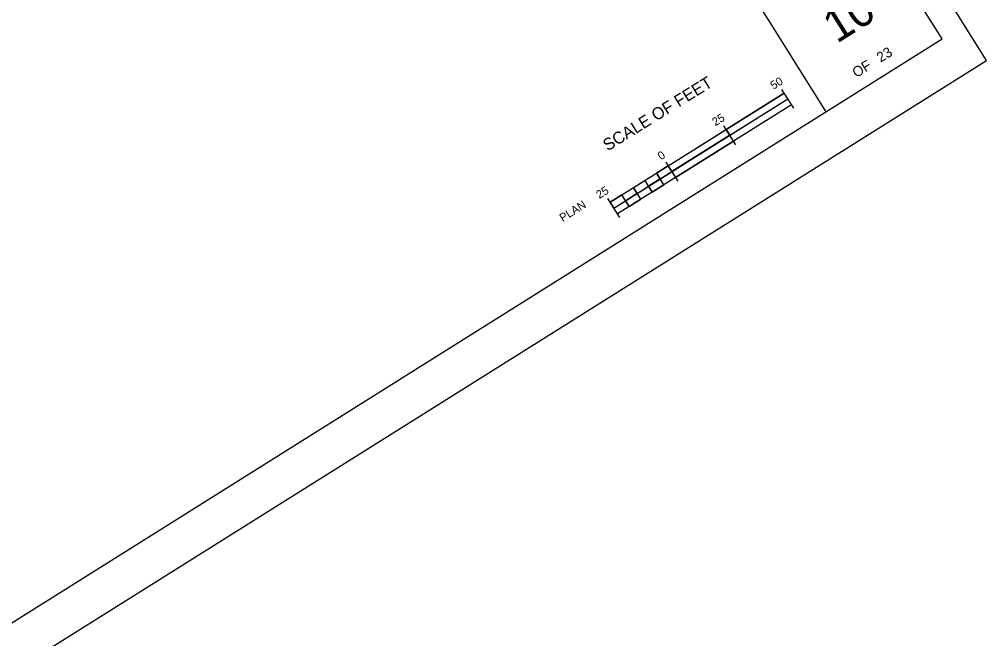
# Model space of a CAD drawing. Extents: x 1667656 to 1668829, y 338796 to 339856.
# Drawn here: x 1668476 to 1668829.2, y 339178.8 to 339404.8 of the extents above; entities that cross this region are included whole.
import ezdxf

# ---------------------------------------------------------------- set-up
doc = ezdxf.new("R2010")
doc.units = 0
for name, color, linetype in [('Asbuilts', 7, 'Continuous'), ('BORDER', 7, 'Continuous'), ('H_V CONTROLS', 7, 'Continuous'), ('PLOT BOUNDARY', 7, 'Continuous')]:
    doc.layers.add(name, color=color, linetype=linetype)

msp = doc.modelspace()

# ---------------------------------------------------------------- linework, layer by layer
at = {"layer": 'Asbuilts'}
msp.add_line((1668755.32, 339377.93), (1668722.75, 339357.5), dxfattribs=at)
at = {"layer": 'BORDER'}
for p, q in [((1668813.03, 339397.69), (1668534.13, 339842.48)), ((1668770.67, 339371.11), (1668491.76, 339815.92)), ((1668135.26, 338972.68), (1668813.03, 339397.67))]:
    msp.add_line(p, q, dxfattribs=at)
at = {"layer": 'H_V CONTROLS'}
for p, q in [((1668758.8, 339372.37), (1668754.49, 339379.25)), ((1668691.78, 339338.08), (1668755.32, 339377.93)), ((1668693.1, 339335.96), (1668756.64, 339375.81)), ((1668757.97, 339373.69), (1668694.43, 339333.85)), ((1668737.62, 339359.08), (1668733.31, 339365.97)), ((1668712.13, 339352.69), (1668716.44, 339345.8)), ((1668711.38, 339344.47), (1668708.72, 339348.71)), ((1668707.14, 339341.81), (1668704.48, 339346.05)), ((1668698.67, 339336.5), (1668696.01, 339340.74)), ((1668702.9, 339339.16), (1668700.25, 339343.39)), ((1668695.26, 339332.52), (1668690.95, 339339.41))]:
    msp.add_line(p, q, dxfattribs=at)
for points in [[(1668735.46, 339362.53), (1668756.64, 339375.81), (1668755.32, 339377.93), (1668734.14, 339364.64), (1668735.46, 339362.53)], [(1668735.46, 339362.53), (1668714.28, 339349.25), (1668715.61, 339347.13), (1668736.79, 339360.41), (1668735.46, 339362.53)], [(1668710.05, 339346.59), (1668714.28, 339349.25), (1668712.96, 339351.36), (1668708.72, 339348.71), (1668710.05, 339346.59)], [(1668705.81, 339343.93), (1668704.48, 339346.05), (1668700.25, 339343.39), (1668701.58, 339341.28), (1668705.81, 339343.93)], [(1668705.81, 339343.93), (1668707.14, 339341.81), (1668711.38, 339344.47), (1668710.05, 339346.59), (1668705.81, 339343.93)], [(1668697.34, 339338.62), (1668696.01, 339340.74), (1668691.78, 339338.08), (1668693.1, 339335.96), (1668697.34, 339338.62)], [(1668697.34, 339338.62), (1668698.67, 339336.5), (1668702.9, 339339.16), (1668701.58, 339341.28), (1668697.34, 339338.62)]]:
    msp.add_lwpolyline(points, dxfattribs=at)
at = {"layer": 'PLOT BOUNDARY'}
msp.add_lwpolyline([(1668109.1, 338938.23), (1668829.24, 339389.78), (1668537.05, 339855.75), (1667816.92, 339404.2)], close=True, dxfattribs=at)

# ---------------------------------------------------------------- texts
at = {"layer": 'BORDER'}
for s, height, p in [('10', 12.097, (1668774.48, 339395.82)), ('23', 3.726, (1668790.52, 339388.94)), ('OF', 3.726, (1668781.66, 339383.39))]:
    msp.add_text(s, height=height, rotation=32.0893, dxfattribs=at).set_placement(p)
at = {"layer": 'H_V CONTROLS'}
for s, height, rotation, p in [('SCALE OF FEET', 4.375, 31.7427, (1668690.84, 339356.6)), ('50', 3, 32.0893, (1668751.42, 339379.1)), ('25', 3, 32.0893, (1668730.16, 339365.77)), ('0', 3, 32.0893, (1668710.31, 339353.32)), ('25', 3, 32.0893, (1668687.8, 339339.21)), ('PLAN', 3, 32.0893, (1668674.42, 339330.82))]:
    msp.add_text(s, height=height, rotation=rotation, dxfattribs=at).set_placement(p)

doc.saveas('drawing.dxf')
